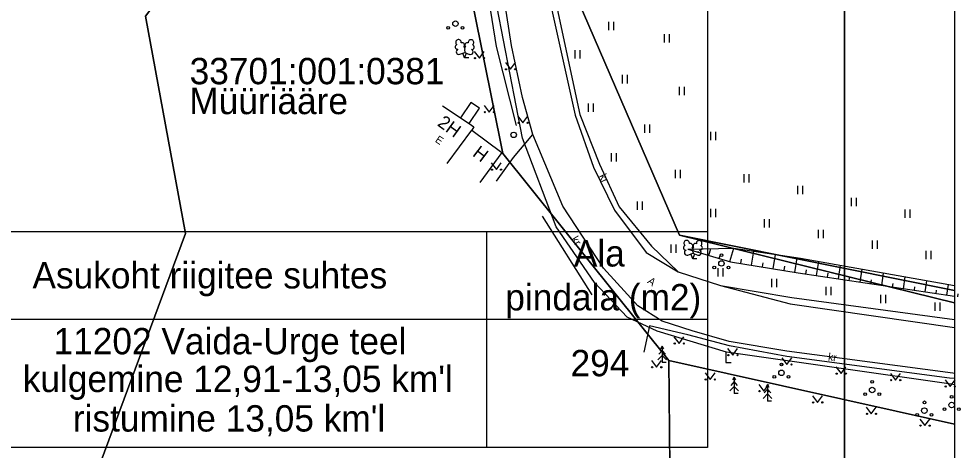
# Model space of a CAD drawing. Extents: x 554947 to 555436, y 6564938 to 6565792.
# Drawn here: x 555307.9 to 555393.6, y 6565441.5 to 6565480.8 of the extents above; entities that cross this region are included whole.
import ezdxf

# ---------------------------------------------------------------- set-up
doc = ezdxf.new("R2010")
doc.units = 0
for name, color, linetype in [('AED', 7, 'Continuous'), ('HALJASTUS', 7, 'Continuous'), ('HOONE', 7, 'Continuous'), ('HOONEDET', 7, 'Continuous'), ('PIIR', 7, 'Continuous'), ('POST', 7, 'Continuous'), ('PR_SIDE', 7, 'Continuous'), ('PUU', 7, 'Continuous'), ('RELJEEF', 7, 'Continuous'), ('TEE', 7, 'Continuous'), ('VORMISTUS_3', 7, 'Continuous')]:
    doc.layers.add(name, color=color, linetype=linetype)

msp = doc.modelspace()

# ---------------------------------------------------------------- linework, layer by layer
at = {"layer": 'AED'}
msp.add_line((555360.091, 6565455.665), (555355.569, 6565462.842), dxfattribs=at)
msp.add_lwpolyline([(555353.187, 6565471.073), (555351.365, 6565478.297), (555349.912, 6565487.399), (555348.203, 6565498.717)], dxfattribs=at)
at = {"layer": 'HALJASTUS'}
for p, q in [((555361.573, 6565480.529), (555361.573, 6565479.768)), ((555362.028, 6565480.529), (555362.028, 6565479.768)), ((555366.634, 6565479.397), (555366.634, 6565478.636)), ((555367.09, 6565479.397), (555367.09, 6565478.636)), ((555358.52, 6565477.955), (555358.52, 6565477.194)), ((555358.975, 6565477.955), (555358.975, 6565477.194)), ((555349.36, 6565477.827), (555349.824, 6565477.22)), ((555349.824, 6565477.22), (555350.269, 6565477.827)), ((555352.185, 6565476.814), (555352.649, 6565476.207)), ((555352.649, 6565476.207), (555353.094, 6565476.814)), ((555362.828, 6565475.689), (555362.828, 6565474.928)), ((555363.283, 6565475.689), (555363.283, 6565474.928)), ((555368.005, 6565474.604), (555368.005, 6565473.843)), ((555368.46, 6565474.604), (555368.46, 6565473.843)), ((555350.258, 6565472.908), (555350.722, 6565472.302)), ((555350.722, 6565472.302), (555351.167, 6565472.908)), ((555359.727, 6565473.103), (555359.727, 6565472.342)), ((555360.182, 6565473.103), (555360.182, 6565472.342)), ((555353.315, 6565471.943), (555353.779, 6565471.336)), ((555353.779, 6565471.336), (555354.224, 6565471.943)), ((555364.839, 6565471.191), (555364.839, 6565470.43)), ((555365.294, 6565471.191), (555365.294, 6565470.43)), ((555370.858, 6565470.499), (555370.858, 6565469.738)), ((555371.313, 6565470.499), (555371.313, 6565469.738)), ((555361.828, 6565468.572), (555361.828, 6565467.811)), ((555362.283, 6565468.572), (555362.283, 6565467.811)), ((555350.905, 6565467.676), (555351.368, 6565467.069)), ((555351.368, 6565467.069), (555351.814, 6565467.676)), ((555367.645, 6565467.053), (555367.645, 6565466.292)), ((555368.1, 6565467.053), (555368.1, 6565466.292)), ((555373.889, 6565466.657), (555373.889, 6565465.895)), ((555374.344, 6565466.657), (555374.344, 6565465.895)), ((555378.771, 6565465.579), (555378.771, 6565464.817)), ((555379.226, 6565465.579), (555379.226, 6565464.817)), ((555383.654, 6565464.5), (555383.654, 6565463.739)), ((555384.109, 6565464.5), (555384.109, 6565463.739)), ((555364.172, 6565464.177), (555364.172, 6565463.416)), ((555364.627, 6565464.177), (555364.627, 6565463.416)), ((555370.845, 6565463.51), (555370.845, 6565462.749)), ((555371.3, 6565463.51), (555371.3, 6565462.749)), ((555388.536, 6565463.422), (555388.536, 6565462.661)), ((555388.991, 6565463.422), (555388.991, 6565462.661)), ((555375.752, 6565462.547), (555375.752, 6565461.786)), ((555376.207, 6565462.547), (555376.207, 6565461.786)), ((555380.658, 6565461.583), (555380.658, 6565460.822)), ((555381.113, 6565461.583), (555381.113, 6565460.822)), ((555367.254, 6565460.24), (555367.254, 6565459.479)), ((555367.709, 6565460.24), (555367.709, 6565459.479)), ((555385.564, 6565460.62), (555385.564, 6565459.859)), ((555386.019, 6565460.62), (555386.019, 6565459.859)), ((555390.47, 6565459.657), (555390.47, 6565458.896)), ((555390.926, 6565459.657), (555390.926, 6565458.896)), ((555371.525, 6565458.083), (555371.525, 6565457.321)), ((555371.98, 6565458.083), (555371.98, 6565457.321)), ((555376.419, 6565457.107), (555376.419, 6565456.346)), ((555376.874, 6565457.107), (555376.874, 6565456.346)), ((555381.367, 6565456.392), (555381.367, 6565455.63)), ((555381.822, 6565456.392), (555381.822, 6565455.63)), ((555386.316, 6565455.676), (555386.316, 6565454.915)), ((555386.771, 6565455.676), (555386.771, 6565454.915)), ((555391.265, 6565454.961), (555391.265, 6565454.2)), ((555391.72, 6565454.961), (555391.72, 6565454.2)), ((555367.533, 6565451.84), (555367.997, 6565451.233)), ((555367.997, 6565451.233), (555368.442, 6565451.84)), ((555372.249, 6565450.508), (555372.249, 6565449.508)), ((555372.419, 6565450.775), (555372.882, 6565450.168)), ((555372.882, 6565450.168), (555373.328, 6565450.775)), ((555365.487, 6565449.67), (555365.951, 6565449.064)), ((555365.951, 6565449.064), (555366.396, 6565449.67)), ((555377.344, 6565449.916), (555377.807, 6565449.309)), ((555377.807, 6565449.309), (555378.253, 6565449.916)), ((555372.249, 6565449.508), (555372.749, 6565449.508)), ((555382.275, 6565449.089), (555382.738, 6565448.482)), ((555382.738, 6565448.482), (555383.184, 6565449.089)), ((555370.362, 6565448.557), (555370.825, 6565447.95)), ((555370.825, 6565447.95), (555371.271, 6565448.557)), ((555387.24, 6565448.5), (555387.703, 6565447.893)), ((555387.703, 6565447.893), (555388.149, 6565448.5)), ((555375.249, 6565447.5), (555375.712, 6565446.893)), ((555375.712, 6565446.893), (555376.158, 6565447.5)), ((555392.205, 6565447.911), (555392.669, 6565447.304)), ((555392.669, 6565447.304), (555393.114, 6565447.911)), ((555380.141, 6565446.467), (555380.604, 6565445.86)), ((555380.604, 6565445.86), (555381.05, 6565446.467)), ((555385.033, 6565445.433), (555385.496, 6565444.826)), ((555385.496, 6565444.826), (555385.942, 6565445.433)), ((555389.914, 6565444.349), (555390.377, 6565443.742)), ((555390.377, 6565443.742), (555390.823, 6565444.349))]:
    msp.add_line(p, q, dxfattribs=at)
for centre in [(555349.423, 6565477.22), (555350.251, 6565477.22), (555352.248, 6565476.207), (555353.077, 6565476.207), (555350.321, 6565472.302), (555351.15, 6565472.302), (555353.378, 6565471.336), (555354.207, 6565471.336), (555350.967, 6565467.069), (555351.796, 6565467.069), (555367.596, 6565451.233), (555368.425, 6565451.233), (555372.481, 6565450.168), (555373.31, 6565450.168), (555365.55, 6565449.064), (555366.378, 6565449.064), (555377.406, 6565449.309), (555378.235, 6565449.309), (555370.424, 6565447.95), (555371.253, 6565447.95), (555382.337, 6565448.482), (555383.166, 6565448.482), (555387.302, 6565447.893), (555388.131, 6565447.893), (555392.268, 6565447.304), (555393.096, 6565447.304), (555375.311, 6565446.893), (555376.14, 6565446.893), (555380.203, 6565445.86), (555381.032, 6565445.86), (555385.095, 6565444.826), (555385.924, 6565444.826), (555389.976, 6565443.742), (555390.805, 6565443.742)]:
    msp.add_circle(centre, 0.055, dxfattribs=at)
at = {"layer": 'HOONE'}
msp.add_line((555346.887, 6565467.616), (555349.13, 6565470.659), dxfattribs=at)
msp.add_lwpolyline([(555346.471, 6565472.875), (555348.897, 6565471.26), (555349.328, 6565470.958), (555349.13, 6565470.659), (555351.876, 6565468.634), (555349.848, 6565465.883)], dxfattribs=at)
at = {"layer": 'HOONEDET'}
msp.add_lwpolyline([(555348.897, 6565471.26), (555349.833, 6565472.665), (555349.029, 6565473.189), (555348.099, 6565471.792)], dxfattribs=at)
at = {"layer": 'PIIR'}
for points in [[(555393.069, 6565456.052), (555368.05, 6565461.11), (555358.8, 6565482.45), (555353.12, 6565523.87), (555393.069, 6565560.972)], [(555393.069, 6565443.872), (555367.06, 6565449.68), (555351.96, 6565468.55), (555343.14, 6565512.46), (555353.12, 6565523.87), (555358.8, 6565482.45), (555368.05, 6565461.11), (555393.069, 6565454.923)], [(555393.069, 6565454.923), (555368.05, 6565461.11), (555393.069, 6565456.052)], [(555367.477, 6565404.752), (555367.06, 6565449.68), (555393.069, 6565443.872)]]:
    msp.add_lwpolyline(points, dxfattribs=at)
for points in [[(555153.01, 6565448.47), (555161.15, 6565451.45), (555173.66, 6565456.03), (555207.29, 6565506.14), (555287.77, 6565518.56), (555302.6, 6565539.71), (555343.14, 6565512.46), (555319.44, 6565481.04), (555323.07, 6565461.26), (555312.9, 6565433.84), (555316.84, 6565372.52), (555318.72, 6565342.57), (555320.51, 6565314.61), (555303.13, 6565302.54), (555208.78, 6565303.3), (555205.15, 6565297.11), (555200.72, 6565310.3), (555206.9, 6565339.44), (555221.23, 6565376.06), (555216.83, 6565392.35), (555207.22, 6565406.57)], [(555319.44, 6565481.04), (555343.14, 6565512.46), (555351.96, 6565468.55), (555367.06, 6565449.68), (555367.76, 6565374.28), (555361.76, 6565374.07), (555316.84, 6565372.52), (555312.9, 6565433.84), (555323.07, 6565461.26)]]:
    msp.add_lwpolyline(points, close=True, dxfattribs=at)
at = {"layer": 'POST'}
msp.add_circle((555352.942, 6565470.231), 0.25, dxfattribs=at)
at = {"layer": 'PR_SIDE'}
msp.add_lwpolyline([(555393.069, 6565447.47), (555392.755, 6565447.532), (555372.326, 6565450.448), (555366.015, 6565452.342), (555363.26, 6565453.626), (555360.292, 6565456.785), (555356.82, 6565461.856), (555353.746, 6565469.93), (555350.28, 6565487.806), (555348.596, 6565498.754), (555346.199, 6565508), (555346.027, 6565508.326), (555343.44, 6565510.968), (555340.158, 6565515.387), (555337.344, 6565518), (555330.24, 6565522.258), (555323.316, 6565526.613), (555319.055, 6565529.304), (555309.687, 6565535.684), (555303.916, 6565540.202)], dxfattribs=at)
at = {"layer": 'PUU'}
for p, q in [((555348.038, 6565477.576), (555348.483, 6565477.751)), ((555348.478, 6565477.241), (555348.303, 6565477.681)), ((555348.478, 6565477.241), (555348.658, 6565477.681)), ((555348.858, 6565477.241), (555348.478, 6565477.241)), ((555348.483, 6565477.751), (555348.923, 6565477.571)), ((555368.805, 6565459.287), (555369.25, 6565459.462)), ((555369.245, 6565458.952), (555369.07, 6565459.392)), ((555369.245, 6565458.952), (555369.425, 6565459.392)), ((555369.25, 6565459.462), (555369.69, 6565459.282)), ((555369.625, 6565458.952), (555369.245, 6565458.952)), ((555366.463, 6565450.595), (555366.163, 6565450.245)), ((555366.463, 6565450.995), (555366.313, 6565450.745)), ((555366.613, 6565450.745), (555366.463, 6565450.995)), ((555366.463, 6565450.995), (555366.463, 6565449.495)), ((555366.763, 6565450.245), (555366.463, 6565450.595)), ((555366.463, 6565450.145), (555366.063, 6565449.745)), ((555366.863, 6565449.745), (555366.463, 6565450.145)), ((555366.823, 6565449.495), (555366.463, 6565449.495)), ((555373.015, 6565448.158), (555372.865, 6565447.908)), ((555373.166, 6565447.908), (555373.015, 6565448.158)), ((555373.015, 6565448.158), (555373.015, 6565446.658)), ((555373.015, 6565447.308), (555372.615, 6565446.908)), ((555373.015, 6565447.758), (555372.715, 6565447.408)), ((555373.316, 6565447.408), (555373.015, 6565447.758)), ((555373.416, 6565446.908), (555373.015, 6565447.308)), ((555376.051, 6565447.081), (555375.751, 6565446.731)), ((555376.051, 6565447.481), (555375.901, 6565447.231)), ((555376.201, 6565447.231), (555376.051, 6565447.481)), ((555376.051, 6565447.481), (555376.051, 6565445.981)), ((555376.351, 6565446.731), (555376.051, 6565447.081)), ((555373.375, 6565446.658), (555373.015, 6565446.658)), ((555376.051, 6565446.631), (555375.651, 6565446.231)), ((555376.451, 6565446.231), (555376.051, 6565446.631)), ((555376.411, 6565445.981), (555376.051, 6565445.981))]:
    msp.add_line(p, q, dxfattribs=at)
for points in [[(555348.483, 6565478.246), (555348.463, 6565478.171), (555348.463, 6565478.151), (555348.473, 6565478.121), (555348.493, 6565478.086), (555348.498, 6565478.066), (555348.483, 6565478.031), (555348.458, 6565477.981), (555348.453, 6565477.956), (555348.458, 6565477.941), (555348.468, 6565477.911), (555348.503, 6565477.851), (555348.508, 6565477.831), (555348.503, 6565477.811), (555348.488, 6565477.776), (555348.483, 6565477.751)], [(555369.25, 6565459.957), (555369.23, 6565459.882), (555369.23, 6565459.862), (555369.24, 6565459.832), (555369.26, 6565459.797), (555369.265, 6565459.777), (555369.25, 6565459.742), (555369.225, 6565459.692), (555369.22, 6565459.667), (555369.225, 6565459.652), (555369.235, 6565459.622), (555369.27, 6565459.562), (555369.275, 6565459.542), (555369.27, 6565459.522), (555369.255, 6565459.487), (555369.25, 6565459.462)]]:
    msp.add_lwpolyline(points, dxfattribs=at)
for centre, radius in [((555347.639, 6565480.37), 0.25), ((555346.989, 6565479.995), 0.125), ((555348.289, 6565479.995), 0.125), ((555371.853, 6565459.273), 0.125), ((555371.203, 6565458.148), 0.125), ((555371.853, 6565458.523), 0.25), ((555372.503, 6565458.148), 0.125), ((555377.316, 6565448.554), 0.25), ((555377.316, 6565449.304), 0.125), ((555376.666, 6565448.179), 0.125), ((555377.966, 6565448.179), 0.125), ((555385.574, 6565446.994), 0.25), ((555385.574, 6565447.744), 0.125), ((555384.924, 6565446.619), 0.125), ((555386.224, 6565446.619), 0.125), ((555392.808, 6565446.376), 0.125), ((555390.326, 6565445.114), 0.25), ((555390.326, 6565445.864), 0.125), ((555392.158, 6565445.251), 0.125), ((555392.808, 6565445.626), 0.25), ((555393.458, 6565445.251), 0.125), ((555389.676, 6565444.739), 0.125), ((555390.976, 6565444.739), 0.125)]:
    msp.add_circle(centre, radius, dxfattribs=at)
for centre, radius, start, end in [((555347.921, 6565478.655), 0.256, 111.50269, 232.51731), ((555347.921, 6565478.655), 0.256, 350.48556, 111.50017), ((555349.057, 6565478.646), 0.256, 67.6168, 188.63142), ((555349.057, 6565478.646), 0.256, 306.59966, 67.61428), ((555347.847, 6565478.244), 0.224, 111.43041, 274.49868), ((555347.951, 6565477.799), 0.237, 111.50143, 291.50036), ((555348.255, 6565478.405), 0.224, 308.50412, 111.57247), ((555348.482, 6565478.008), 0.237, 66.76552, 111.50149), ((555348.718, 6565478.4), 0.225, 67.7016, 230.51262), ((555349.013, 6565477.791), 0.237, 247.61661, 67.61554), ((555349.124, 6565478.234), 0.224, 264.6183, 67.68657), ((555368.614, 6565459.955), 0.224, 111.43041, 274.49868), ((555368.688, 6565460.366), 0.256, 111.50269, 232.51731), ((555368.688, 6565460.366), 0.256, 350.48556, 111.50017), ((555369.023, 6565460.115), 0.224, 308.50412, 111.57247), ((555369.249, 6565459.719), 0.237, 66.76552, 111.50149), ((555369.486, 6565460.111), 0.225, 67.7016, 230.51262), ((555369.824, 6565460.357), 0.256, 67.6168, 188.63142), ((555369.892, 6565459.945), 0.224, 264.6183, 67.68657), ((555369.824, 6565460.357), 0.256, 306.59966, 67.61428), ((555368.719, 6565459.51), 0.237, 111.50143, 291.50036), ((555369.78, 6565459.502), 0.237, 247.61661, 67.61554)]:
    msp.add_arc(centre, radius, start, end, dxfattribs=at)
at = {"layer": 'RELJEEF'}
for p, q in [((555372.62, 6565458.694), (555372.979, 6565459.925)), ((555369.74, 6565459.534), (555369.767, 6565459.626)), ((555370.7, 6565459.254), (555370.88, 6565459.87)), ((555371.66, 6565458.974), (555371.741, 6565459.251)), ((555374.592, 6565458.362), (555374.804, 6565459.646)), ((555376.565, 6565458.036), (555376.781, 6565459.343)), ((555373.605, 6565458.525), (555373.668, 6565458.907)), ((555375.578, 6565458.199), (555375.643, 6565458.588)), ((555377.552, 6565457.873), (555377.617, 6565458.269)), ((555378.538, 6565457.71), (555378.758, 6565459.041)), ((555380.515, 6565457.409), (555380.709, 6565458.701)), ((555382.493, 6565457.112), (555382.679, 6565458.35)), ((555379.527, 6565457.557), (555379.586, 6565457.953)), ((555381.504, 6565457.261), (555381.561, 6565457.64)), ((555384.471, 6565456.816), (555384.649, 6565457.999)), ((555386.449, 6565456.519), (555386.618, 6565457.648)), ((555383.482, 6565456.964), (555383.537, 6565457.327)), ((555385.46, 6565456.667), (555385.512, 6565457.014)), ((555387.438, 6565456.371), (555387.488, 6565456.701)), ((555388.427, 6565456.222), (555388.588, 6565457.297)), ((555390.405, 6565455.926), (555390.558, 6565456.946)), ((555392.383, 6565455.629), (555392.528, 6565456.595)), ((555389.416, 6565456.074), (555389.463, 6565456.388)), ((555391.394, 6565455.777), (555391.438, 6565456.075)), ((555393.372, 6565455.481), (555393.414, 6565455.762))]:
    msp.add_line(p, q, dxfattribs=at)
for points in [[(555368.78, 6565459.814), (555372.971, 6565459.927), (555379.063, 6565458.994), (555393.069, 6565456.498)], [(555368.78, 6565459.814), (555372.666, 6565458.68), (555378.843, 6565457.66), (555393.069, 6565455.526)]]:
    msp.add_lwpolyline(points, dxfattribs=at)
at = {"layer": 'TEE'}
for points in [[(555360.017, 6565532.032), (555356.722, 6565529.611), (555352.039, 6565526.571), (555350.841, 6565524.289), (555349.902, 6565522.246), (555349.37, 6565518.742), (555349.968, 6565514.969), (555351.498, 6565509.514), (555352.399, 6565505.44), (555355.185, 6565489.693), (555356.356, 6565481.874), (555358.536, 6565472.027), (555360.203, 6565467.288), (555362.127, 6565463.387), (555364.998, 6565459.532), (555367.923, 6565457.754), (555371.76, 6565456.513), (555378.11, 6565454.853), (555393.069, 6565452.684)], [(555393.069, 6565448.493), (555392.904, 6565448.521), (555377.792, 6565450.52), (555372.547, 6565451.424), (555369.187, 6565452.37), (555366.443, 6565453.255), (555364.23, 6565454.662), (555361.13, 6565458.083), (555357.411, 6565463.749), (555354.693, 6565470.258), (555353.748, 6565473.64), (555352.733, 6565478.362), (555351.267, 6565487.961), (555349.516, 6565498.784), (555347.141, 6565508.358), (555345.332, 6565511.802), (555341.773, 6565516.752), (555338.53, 6565519.62), (555330.669, 6565524.333), (555325.029, 6565527.171), (555324.447, 6565527.997), (555320.204, 6565530.941)], [(555358.969, 6565483.478), (555358.843, 6565483.458), (555356.63, 6565483.037), (555358.965, 6565472.102), (555360.762, 6565467.568), (555362.536, 6565463.692), (555365.5, 6565460.084), (555367.923, 6565457.754)], [(555351.364, 6565466.022), (555352.93, 6565468.179), (555354.693, 6565470.258)], [(555371.76, 6565456.513), (555378.274, 6565455.429), (555393.069, 6565453.404)], [(555393.069, 6565448.031), (555392.602, 6565448.077), (555377.792, 6565450.042), (555372.591, 6565451.027), (555368.793, 6565452.002), (555365.308, 6565452.827), (555364.788, 6565450.448)]]:
    msp.add_lwpolyline(points, dxfattribs=at)
at = {"layer": 'VORMISTUS_3'}
for p, q in [((555350.469, 6565461.442), (555350.469, 6565441.752)), ((555205.569, 6565453.442), (555370.569, 6565453.442))]:
    msp.add_line(p, q, dxfattribs=at)
for points in [[(555183.069, 6565701.752), (555393.069, 6565701.752), (555393.069, 6565404.752), (555183.069, 6565404.752)], [(555193.069, 6565415.752), (555383.069, 6565415.752), (555383.069, 6565690.752), (555193.069, 6565690.752)], [(555193.069, 6565690.752), (555383.069, 6565690.752), (555383.069, 6565415.752), (555193.069, 6565415.752)], [(555370.569, 6565441.752), (555205.569, 6565441.752), (555205.569, 6565651.752), (555370.569, 6565651.752)], [(555205.569, 6565461.442), (555370.569, 6565461.442), (555370.569, 6565441.752), (555205.569, 6565441.752)]]:
    msp.add_lwpolyline(points, close=True, dxfattribs=at)

# ---------------------------------------------------------------- texts
at = {"layer": 'HOONE'}
for s, height, rotation, p in [('2H', 1.2, 324.17294, (555345.923, 6565471.127)), ('E', 0.7, 326.34193, (555345.732, 6565469.638)), ('H', 1.2, 322.94839, (555349.121, 6565468.379))]:
    msp.add_text(s, height=height, rotation=rotation, dxfattribs=at).set_placement(p)
at = {"layer": 'PIIR'}
for s, p in [('33701:001:0381', (555323.446, 6565474.845)), ('Müüriääre', (555323.415, 6565472.122))]:
    msp.add_text(s, height=2.4, dxfattribs=at).set_placement(p)
at = {"layer": 'TEE'}
for s, rotation, p in [('kr', 296.21546, (555360.69, 6565466.483)), ('kr', 302.10529, (555358.156, 6565460.742)), ('A', 323.81797, (555365.054, 6565456.781)), ('kr', 352.39623, (555381.529, 6565449.681))]:
    msp.add_text(s, height=0.7, rotation=rotation, dxfattribs=at).set_placement(p)
at = {"layer": 'VORMISTUS_3'}
for s, p in [('Ala', (555358.42, 6565458.242)), ('Asukoht riigitee suhtes ', (555309.141, 6565456.242)), ('pindala (m2)', (555352.181, 6565454.242)), ('11202 Vaida-Urge teel', (555311.061, 6565450.242)), ('294', (555358.119, 6565448.242)), ("kulgemine 12,91-13,05 km'l", (555308.258, 6565446.806)), ("ristumine 13,05 km'l", (555312.818, 6565443.206))]:
    msp.add_text(s, height=2.4, dxfattribs=at).set_placement(p)

doc.saveas('drawing.dxf')
